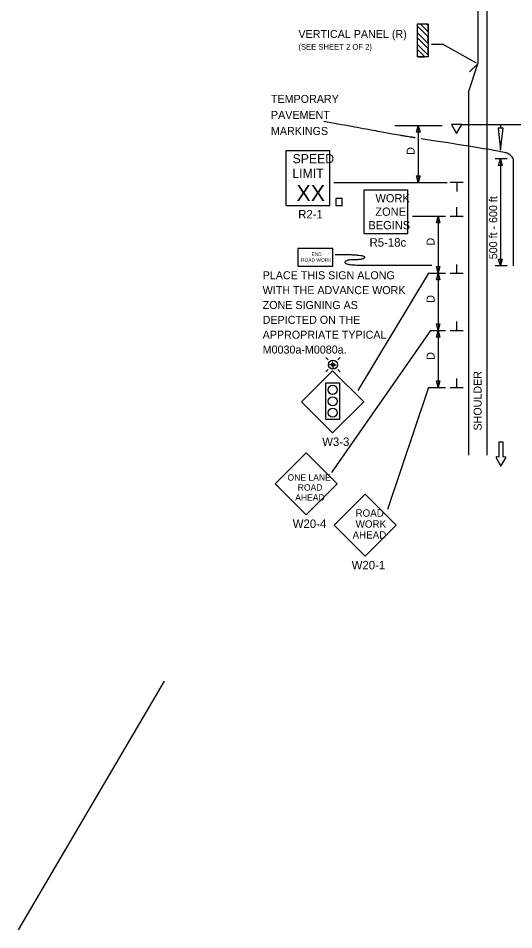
# Model space of a CAD drawing. Extents: x 16520 to 18479, y 5662 to 6927.
# Drawn here: x 16520 to 16953, y 5662 to 6460 of the extents above; entities that cross this region are included whole.
import ezdxf

# ---------------------------------------------------------------- set-up
doc = ezdxf.new("R2010")
doc.units = 0
for name, color, linetype in [('ALI_LEGAL_EX', 7, 'Continuous'), ('MT_SCRATCH_LEVEL_E', 7, 'Continuous'), ('PAVT_EDGE_EX', 7, 'Continuous'), ('TRAFFIC_SIGNS_PR', 7, 'Continuous'), ('TYPICAL_TEXT_DIMEN_PR', 7, 'Continuous')]:
    doc.layers.add(name, color=color, linetype=linetype)

msp = doc.modelspace()

# ---------------------------------------------------------------- linework, layer by layer
at = {"layer": 'ALI_LEGAL_EX'}
msp.add_lwpolyline([(16952.78, 6336.76), (16952.78, 6243.13)], dxfattribs=at)
at = {"layer": 'MT_SCRATCH_LEVEL_E'}
for p, q in [((16943.98, 6089.01), (16940.24, 6089.01)), ((16940.24, 6089.01), (16940.24, 6075.76)), ((16943.98, 6089.01), (16940.24, 6089.01)), ((16940.24, 6089.01), (16940.24, 6075.76)), ((16943.98, 6075.76), (16943.98, 6089.01)), ((16943.98, 6075.76), (16943.98, 6089.01)), ((16940.24, 6075.76), (16938.46, 6076.07)), ((16940.24, 6075.76), (16938.46, 6076.07)), ((16945.76, 6076.07), (16943.98, 6075.76)), ((16945.76, 6076.07), (16943.98, 6075.76)), ((16937.98, 6075.39), (16942.13, 6068.15)), ((16937.98, 6075.39), (16942.13, 6068.15)), ((16942.13, 6068.15), (16946.24, 6075.39)), ((16942.13, 6068.15), (16946.24, 6075.39))]:
    msp.add_line(p, q, dxfattribs=at)
for centre, start, end in [((16938.39, 6075.61), 80.03619, 209.77312), ((16938.39, 6075.61), 80.03619, 209.77312), ((16945.83, 6075.61), 330.42484, 99.96381), ((16945.83, 6075.61), 330.42484, 99.96381)]:
    msp.add_arc(centre, 0.463, start, end, dxfattribs=at)
at = {"layer": 'PAVT_EDGE_EX'}
for p, q in [((16929.78, 6899.43), (16929.78, 6077.5)), ((16921.78, 6551.35), (16921.78, 6419.96)), ((16913.78, 6395.26), (16921.78, 6419.96)), ((16921.78, 6419.96), (16914.71, 6412.89)), ((16913.78, 6395.26), (16913.78, 6077.5))]:
    msp.add_line(p, q, dxfattribs=at)
at = {"layer": 'TRAFFIC_SIGNS_PR'}
for p, q in [((16878.5, 6454.77), (16868.9, 6454.77)), ((16868.9, 6454.77), (16868.9, 6425.97)), ((16878.5, 6454.77), (16868.9, 6454.77)), ((16868.9, 6454.77), (16868.9, 6425.97)), ((16878.5, 6443.5), (16868.9, 6453.1)), ((16878.5, 6443.5), (16868.9, 6453.1)), ((16878.5, 6448.02), (16871.76, 6454.77)), ((16878.5, 6448.02), (16871.76, 6454.77)), ((16878.5, 6453.68), (16877.41, 6454.77)), ((16878.5, 6453.68), (16877.41, 6454.77)), ((16878.5, 6454.77), (16878.5, 6425.97)), ((16878.5, 6454.77), (16878.5, 6425.97)), ((16878.5, 6437.84), (16868.9, 6447.44)), ((16878.5, 6437.84), (16868.9, 6447.44)), ((16878.5, 6433.32), (16868.9, 6442.92)), ((16878.5, 6433.32), (16868.9, 6442.92)), ((16878.5, 6427.66), (16868.9, 6437.26)), ((16878.5, 6427.66), (16868.9, 6437.26)), ((16875.67, 6425.97), (16868.9, 6432.73)), ((16875.67, 6425.97), (16868.9, 6432.73)), ((16870.01, 6425.97), (16868.9, 6427.08)), ((16870.01, 6425.97), (16868.9, 6427.08)), ((16878.5, 6425.97), (16868.9, 6425.97)), ((16878.5, 6425.97), (16868.9, 6425.97)), ((16907.78, 6366.76), (16999.78, 6366.76)), ((16941.78, 6366.76), (16941.78, 6363.74)), ((16754.2, 6344.1), (16792.6, 6344.1)), ((16754.2, 6296.1), (16754.2, 6344.1)), ((16792.6, 6296.1), (16792.6, 6344.1)), ((16822.4, 6271.44), (16822.4, 6309.84)), ((16822.4, 6309.84), (16860.8, 6309.84)), ((16860.8, 6271.44), (16860.8, 6309.84)), ((16754.2, 6296.1), (16792.6, 6296.1)), ((16822.4, 6271.44), (16860.8, 6271.44)), ((16790.96, 6161.07), (16788.92, 6163.11)), ((16795.24, 6156.79), (16792.36, 6156.79)), ((16795.24, 6156.79), (16795.24, 6159.67)), ((16795.24, 6156.79), (16795.24, 6152.85)), ((16795.24, 6156.79), (16798.11, 6156.79)), ((16799.52, 6161.07), (16801.55, 6163.11)), ((16794.95, 6151.39), (16767.8, 6124.23)), ((16790.96, 6152.51), (16788.92, 6150.48)), ((16822.1, 6124.23), (16794.95, 6151.39)), ((16801.55, 6150.48), (16799.52, 6152.51)), ((16767.8, 6124.23), (16794.95, 6097.08)), ((16794.95, 6097.08), (16822.1, 6124.23)), ((16771.91, 6079.67), (16744.76, 6052.52)), ((16799.06, 6052.52), (16771.91, 6079.67)), ((16744.76, 6052.52), (16771.91, 6025.37)), ((16771.91, 6025.37), (16799.06, 6052.52)), ((16823.42, 6043.45), (16796.27, 6016.3)), ((16850.57, 6016.3), (16823.42, 6043.45)), ((16796.27, 6016.3), (16823.42, 5989.14)), ((16823.42, 5989.14), (16850.57, 6016.3))]:
    msp.add_line(p, q, dxfattribs=at)
for points in [[(16878.5, 6443.5), (16868.9, 6453.1), (16868.9, 6447.44), (16878.5, 6437.84)], [(16878.5, 6443.5), (16868.9, 6453.1), (16868.9, 6447.44), (16878.5, 6437.84)], [(16877.41, 6454.77), (16871.76, 6454.77), (16878.5, 6448.02), (16878.5, 6453.68)], [(16877.41, 6454.77), (16871.76, 6454.77), (16878.5, 6448.02), (16878.5, 6453.68)], [(16878.5, 6433.32), (16868.9, 6442.92), (16868.9, 6437.26), (16878.5, 6427.66)], [(16878.5, 6433.32), (16868.9, 6442.92), (16868.9, 6437.26), (16878.5, 6427.66)], [(16868.9, 6432.73), (16868.9, 6427.08), (16870.01, 6425.97), (16875.67, 6425.97)], [(16868.9, 6432.73), (16868.9, 6427.08), (16870.01, 6425.97), (16875.67, 6425.97)], [(16898.78, 6366.76), (16903.28, 6358.97), (16907.78, 6366.76)], [(16939.53, 6363.74), (16941.78, 6344.32), (16944.03, 6363.74)], [(16797.61, 6296.1), (16803.21, 6296.1), (16803.21, 6302.27), (16797.61, 6302.27)], [(16764.44, 6242.96), (16795.16, 6242.96), (16795.16, 6258.32), (16764.44, 6258.32)], [(16801.01, 6108.78), (16789.01, 6108.78), (16789.01, 6140.78), (16801.01, 6140.78)]]:
    msp.add_lwpolyline(points, close=True, dxfattribs=at)
for centre, radius in [((16795.24, 6156.79), 3.94), ((16795.24, 6156.79), 1.28), ((16795.01, 6134.78), 4), ((16795.01, 6124.78), 4), ((16795.01, 6114.78), 4)]:
    msp.add_circle(centre, radius, dxfattribs=at)
at = {"layer": 'TYPICAL_TEXT_DIMEN_PR'}
for p, q in [((16891.56, 6436.77), (16881.31, 6436.77)), ((16891.56, 6436.77), (16881.31, 6436.77)), ((16920.82, 6420.54), (16891.56, 6436.77)), ((16920.82, 6420.54), (16891.56, 6436.77)), ((16849.43, 6366.06), (16890.78, 6366.06)), ((16868.21, 6360.2), (16869.78, 6366.06)), ((16869.78, 6366.06), (16869.78, 6316.06)), ((16869.78, 6366.06), (16871.35, 6360.2)), ((16869.78, 6360.2), (16868.21, 6360.2)), ((16871.35, 6360.2), (16869.78, 6360.2)), ((16950.89, 6339.42), (16952.6, 6337.06)), ((16947.46, 6336.76), (16936.94, 6336.76)), ((16940.05, 6330.9), (16941.62, 6336.76)), ((16941.62, 6336.76), (16941.62, 6243.13)), ((16941.62, 6336.76), (16943.19, 6330.9)), ((16941.62, 6330.9), (16940.05, 6330.9)), ((16943.19, 6330.9), (16941.62, 6330.9)), ((16796.1, 6316.06), (16895.07, 6316.06)), ((16869.78, 6316.06), (16868.21, 6321.92)), ((16868.21, 6321.92), (16869.78, 6321.92)), ((16869.78, 6321.92), (16871.35, 6321.92)), ((16871.35, 6321.92), (16869.78, 6316.06)), ((16909.03, 6316.06), (16897.78, 6316.06)), ((16903.41, 6316.06), (16903.41, 6308.28)), ((16903.41, 6286.76), (16903.41, 6294.55)), ((16864.86, 6286.76), (16893.53, 6286.76)), ((16885.64, 6280.9), (16887.21, 6286.76)), ((16887.21, 6286.76), (16887.21, 6236.76)), ((16887.21, 6286.76), (16888.78, 6280.9)), ((16897.78, 6286.76), (16909.03, 6286.76)), ((16887.21, 6280.9), (16885.64, 6280.9)), ((16888.78, 6280.9), (16887.21, 6280.9)), ((16903.41, 6236.76), (16903.41, 6244.55)), ((16941.62, 6243.13), (16940.05, 6249)), ((16940.05, 6249), (16941.62, 6249)), ((16941.62, 6249), (16943.19, 6249)), ((16943.19, 6249), (16941.62, 6243.13)), ((16878.62, 6236.76), (16817.09, 6134.24)), ((16878.62, 6236.76), (16893.53, 6236.76)), ((16887.21, 6236.76), (16885.64, 6242.63)), ((16885.64, 6242.63), (16887.21, 6242.63)), ((16885.64, 6230.9), (16887.21, 6236.76)), ((16887.21, 6242.63), (16888.78, 6242.63)), ((16888.78, 6242.63), (16887.21, 6236.76)), ((16887.21, 6236.76), (16887.21, 6186.76)), ((16887.21, 6236.76), (16888.78, 6230.9)), ((16897.78, 6236.76), (16909.03, 6236.76)), ((16947.46, 6243.13), (16936.94, 6243.13)), ((16887.21, 6230.9), (16885.64, 6230.9)), ((16888.78, 6230.9), (16887.21, 6230.9)), ((16887.21, 6186.76), (16885.64, 6192.63)), ((16885.64, 6192.63), (16887.21, 6192.63)), ((16887.21, 6192.63), (16888.78, 6192.63)), ((16888.78, 6192.63), (16887.21, 6186.76)), ((16903.41, 6186.76), (16903.41, 6194.55)), ((16880.53, 6186.76), (16793.82, 6062.59)), ((16880.53, 6186.76), (16893.53, 6186.76)), ((16885.64, 6180.9), (16887.21, 6186.76)), ((16887.21, 6180.9), (16885.64, 6180.9)), ((16887.21, 6186.76), (16887.21, 6136.76)), ((16887.21, 6186.76), (16888.78, 6180.9)), ((16888.78, 6180.9), (16887.21, 6180.9)), ((16897.78, 6186.76), (16909.03, 6186.76)), ((16887.21, 6136.76), (16885.64, 6142.63)), ((16885.64, 6142.63), (16887.21, 6142.63)), ((16887.21, 6142.63), (16888.78, 6142.63)), ((16888.78, 6142.63), (16887.21, 6136.76)), ((16903.41, 6136.76), (16903.41, 6144.55)), ((16878.62, 6136.76), (16842.81, 6030.14)), ((16878.62, 6136.76), (16893.53, 6136.76)), ((16897.78, 6136.76), (16909.03, 6136.76)), ((16647.75, 5880), (16520.14, 5662.47))]:
    msp.add_line(p, q, dxfattribs=at)
for points, degree in [([(16787.14, 6369.89), (16852.52, 6357.73), (16860.07, 6356.58), (16867.03, 6355.51)], 2), ([(16872.42, 6354.67), (16943.06, 6343.72), (16949.06, 6341.58), (16950.77, 6339.57), (16950.81, 6339.52), (16950.85, 6339.47), (16950.89, 6339.42)], 3), ([(16797.27, 6253.26), (16822.86, 6253.26), (16822.86, 6248.55), (16805.64, 6248.55), (16805.64, 6243.84), (16838.64, 6243.84), (16881.57, 6243.84)], 2)]:
    msp.add_open_spline(points, degree=degree, dxfattribs=at)

# ---------------------------------------------------------------- texts
at = {"layer": 'TRAFFIC_SIGNS_PR'}
for s, height, p in [('SPEED', 8, (16759.96, 6332.96)), ('LIMIT', 8, (16759.8, 6320.16)), ('XX', 14.031, (16763.31, 6299.86)), ('WORK', 7.217, (16832.4, 6298.81)), ('R2-1', 7.44, (16764.87, 6284.66)), ('ZONE', 7.217, (16832.28, 6287)), ('BEGINS', 7.217, (16826.21, 6275.19)), ('R5-18c', 7.44, (16827.21, 6260)), ('END', 3.065, (16776.44, 6251.86)), ('ROAD WORK', 3.065, (16767.33, 6246.76)), ('PLACE THIS SIGN ALONG', 7, (16733.81, 6231.5)), ('WITH THE ADVANCE WORK', 7, (16733.81, 6218.5)), ('ZONE SIGNING AS', 7, (16733.81, 6205.5)), ('DEPICTED ON THE', 7, (16733.81, 6192.5)), ('APPROPRIATE TYPICAL', 7, (16733.81, 6179.5)), ('M0030a-M0080a.', 7, (16733.81, 6166.5)), ('W3-3', 7.44, (16785.82, 6085.64)), ('ONE LANE', 5.6, (16755.5, 6055.39)), ('ROAD', 5.6, (16764.45, 6046.59)), ('AHEAD', 5.6, (16762.2, 6037.79)), ('ROAD', 6.4, (16814.96, 6023.83)), ('W20-4', 7.44, (16760.09, 6013.93)), ('WORK', 6.4, (16815.07, 6014.23)), ('AHEAD', 6.4, (16812.38, 6004.63)), ('W20-1', 7.44, (16811.59, 5977.7))]:
    msp.add_text(s, height=height, dxfattribs=at).set_placement(p)
at = {"layer": 'TYPICAL_TEXT_DIMEN_PR'}
for s, height, p in [('VERTICAL PANEL (R)', 7, (16765.06, 6442.54)), ('VERTICAL PANEL (R)', 7, (16765.06, 6442.54)), ('(SEE SHEET 2 OF 2)', 5, (16765.06, 6432.28)), ('(SEE SHEET 2 OF 2)', 5, (16765.06, 6432.28)), ('TEMPORARY', 7, (16741.04, 6385.74)), ('PAVEMENT', 7, (16741.04, 6371.74)), ('MARKINGS', 7, (16741.04, 6357.74))]:
    msp.add_text(s, height=height, dxfattribs=at).set_placement(p)
for s, p in [('D', (16866.65, 6340.28)), ('500 ft - 600 ft', (16938.8, 6248.99)), ('D', (16884.07, 6260.98)), ('D', (16884.07, 6210.98)), ('D', (16884.07, 6160.98)), ('SHOULDER', (16925.2, 6099.18))]:
    msp.add_text(s, height=7, rotation=90, dxfattribs=at).set_placement(p)

doc.saveas('drawing.dxf')
